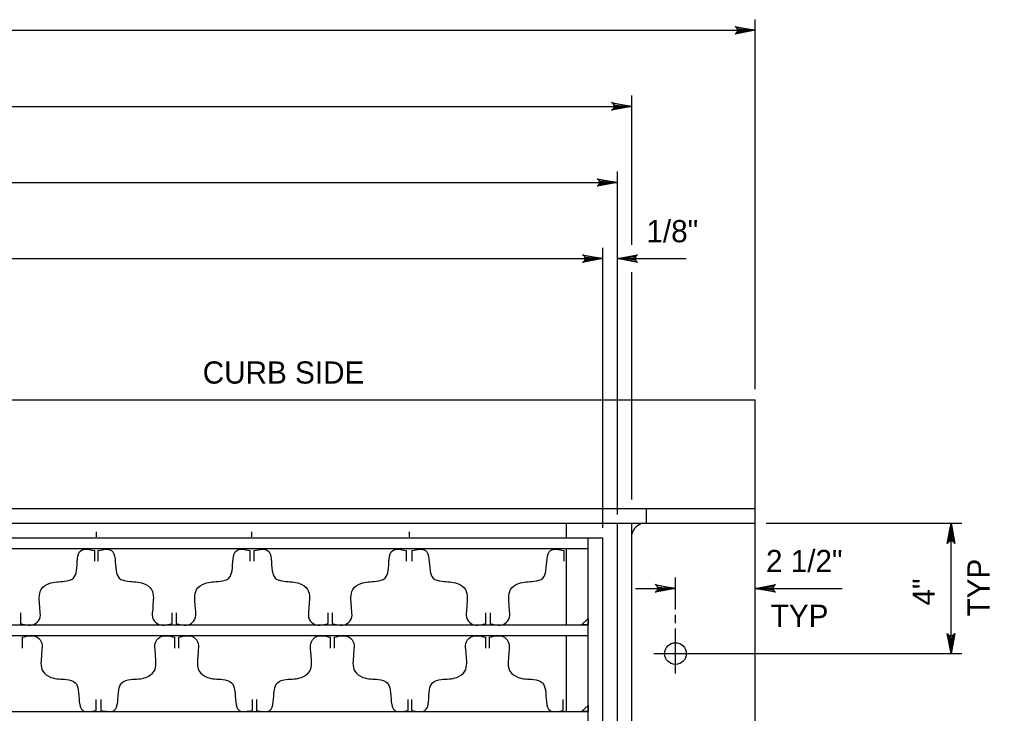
# Model space of a CAD drawing. Extents: x 0.71 to 8.05, y -5.67 to 4.31.
# Drawn here: x 5.033 to 7.656, y 2.355 to 4.233 of the extents above; entities that cross this region are included whole.
import ezdxf

# ---------------------------------------------------------------- set-up
doc = ezdxf.new("R2010")
doc.units = 0
for name, color, linetype in [('DETL-DIMS', 7, 'Continuous'), ('DETL-LINE', 7, 'Continuous'), ('DETL-NOTE', 7, 'Continuous')]:
    doc.layers.add(name, color=color, linetype=linetype)

msp = doc.modelspace()

# ---------------------------------------------------------------- linework, layer by layer
at = {"layer": 'DETL-DIMS'}
for p, q in [((7.0228, 3.233), (7.0228, 4.233)), ((2.1992, 4.2036), (7.0228, 4.2036)), ((6.6892, 3.6228), (6.6892, 4.0271)), ((2.5328, 3.9977), (6.6892, 3.9977)), ((6.6498, 2.8936), (6.6498, 3.8213)), ((2.5722, 3.7918), (6.6498, 3.7918)), ((6.6104, 2.8572), (6.6104, 3.6154)), ((2.6116, 3.586), (6.6104, 3.586)), ((6.6498, 3.586), (6.8363, 3.586)), ((6.6892, 2.934), (6.6892, 3.5492)), ((7.0522, 2.8701), (7.5816, 2.8701)), ((7.5522, 2.5171), (7.5522, 2.8701)), ((6.8069, 2.6365), (6.8069, 2.723)), ((6.6992, 2.6936), (6.8069, 2.6936)), ((7.0228, 2.6936), (7.2581, 2.6936)), ((6.8069, 2.5994), (6.8069, 2.6221)), ((6.8069, 2.4632), (6.8069, 2.5849)), ((6.7481, 2.5171), (7.5816, 2.5171))]:
    msp.add_line(p, q, dxfattribs=at)
for points in [[(7.0228, 4.2036), (6.9679, 4.1933), (6.9722, 4.1963), (6.9743, 4.1999), (6.975, 4.2036), (6.9743, 4.2073), (6.9722, 4.211), (6.9679, 4.2139), (7.0228, 4.2036), (6.9722, 4.211), (6.9743, 4.2073), (7.0228, 4.2036), (6.975, 4.2036), (6.9743, 4.1999), (7.0228, 4.2036), (6.9722, 4.1963)], [(6.6892, 3.9977), (6.6344, 3.9875), (6.6386, 3.9904), (6.6408, 3.9941), (6.6414, 3.9977), (6.6408, 4.0014), (6.6386, 4.0051), (6.6344, 4.008), (6.6892, 3.9977), (6.6386, 4.0051), (6.6408, 4.0014), (6.6892, 3.9977), (6.6414, 3.9977), (6.6408, 3.9941), (6.6892, 3.9977), (6.6386, 3.9904)], [(6.6498, 3.7918), (6.595, 3.7816), (6.5992, 3.7845), (6.6014, 3.7882), (6.602, 3.7918), (6.6014, 3.7955), (6.5992, 3.7992), (6.595, 3.8021), (6.6498, 3.7918), (6.5992, 3.7992), (6.6014, 3.7955), (6.6498, 3.7918), (6.602, 3.7918), (6.6014, 3.7882), (6.6498, 3.7918), (6.5992, 3.7845)], [(6.6104, 3.586), (6.5556, 3.5757), (6.5598, 3.5786), (6.562, 3.5823), (6.5626, 3.586), (6.562, 3.5896), (6.5598, 3.5933), (6.5556, 3.5962), (6.6104, 3.586), (6.5598, 3.5933), (6.562, 3.5896), (6.6104, 3.586), (6.5626, 3.586), (6.562, 3.5823), (6.6104, 3.586), (6.5598, 3.5786)], [(6.6498, 3.586), (6.7046, 3.5962), (6.7004, 3.5933), (6.6982, 3.5896), (6.6976, 3.586), (6.6982, 3.5823), (6.7004, 3.5786), (6.7046, 3.5757), (6.6498, 3.586), (6.7004, 3.5786), (6.6982, 3.5823), (6.6498, 3.586), (6.6976, 3.586), (6.6982, 3.5896), (6.6498, 3.586), (6.7004, 3.5933)], [(7.5522, 2.8701), (7.5625, 2.8153), (7.5595, 2.8195), (7.5558, 2.8217), (7.5522, 2.8223), (7.5485, 2.8217), (7.5448, 2.8195), (7.5419, 2.8153), (7.5522, 2.8701), (7.5448, 2.8195), (7.5485, 2.8217), (7.5522, 2.8701), (7.5522, 2.8223), (7.5558, 2.8217), (7.5522, 2.8701), (7.5595, 2.8195)], [(6.8069, 2.6936), (6.752, 2.6833), (6.7563, 2.6863), (6.7585, 2.6899), (6.7591, 2.6936), (6.7585, 2.6973), (6.7563, 2.701), (6.752, 2.7039), (6.8069, 2.6936), (6.7563, 2.701), (6.7585, 2.6973), (6.8069, 2.6936), (6.7591, 2.6936), (6.7585, 2.6899), (6.8069, 2.6936), (6.7563, 2.6863)], [(7.0228, 2.6936), (7.0776, 2.7039), (7.0734, 2.701), (7.0712, 2.6973), (7.0706, 2.6936), (7.0712, 2.6899), (7.0734, 2.6863), (7.0776, 2.6833), (7.0228, 2.6936), (7.0734, 2.6863), (7.0712, 2.6899), (7.0228, 2.6936), (7.0706, 2.6936), (7.0712, 2.6973), (7.0228, 2.6936), (7.0734, 2.701)], [(7.5522, 2.5171), (7.5419, 2.572), (7.5448, 2.5677), (7.5485, 2.5656), (7.5522, 2.5649), (7.5558, 2.5656), (7.5595, 2.5677), (7.5625, 2.572), (7.5522, 2.5171), (7.5595, 2.5677), (7.5558, 2.5656), (7.5522, 2.5171), (7.5522, 2.5649), (7.5485, 2.5656), (7.5522, 2.5171), (7.5448, 2.5677)]]:
    msp.add_lwpolyline(points, dxfattribs=at)
at = {"layer": 'DETL-LINE'}
for p, q in [((2.1992, 3.2036), (7.0228, 3.2036)), ((7.0228, 0.546), (7.0228, 3.2036)), ((2.1992, 2.9095), (7.0228, 2.9095)), ((6.7286, 2.8701), (6.7286, 2.9095)), ((2.1992, 2.8701), (7.0228, 2.8701)), ((6.5122, 2.8307), (6.5122, 2.8701)), ((6.6498, 0.8795), (6.6498, 2.8701)), ((6.6892, 0.8795), (6.6892, 2.8701)), ((5.2412, 2.8331), (5.2412, 2.8468)), ((5.6618, 2.8331), (5.6618, 2.8468)), ((6.0874, 2.8331), (6.0874, 2.8468)), ((2.6116, 2.8307), (6.6104, 2.8307)), ((6.571, 0.9189), (6.571, 2.8307)), ((6.571, 0.9189), (6.571, 2.8307)), ((6.6104, 0.9189), (6.6104, 2.8307)), ((2.651, 2.8013), (6.571, 2.8013)), ((5.2358, 2.7965), (5.2358, 2.7671)), ((5.2461, 2.7671), (5.2461, 2.7965)), ((5.6565, 2.7965), (5.6565, 2.7671)), ((5.6682, 2.7671), (5.6682, 2.7965)), ((6.0785, 2.7965), (6.0785, 2.7671)), ((6.0949, 2.7671), (6.0949, 2.7965)), ((6.5052, 2.7965), (6.5052, 2.7671)), ((6.5122, 2.5954), (6.5122, 2.8013)), ((5.0363, 2.6279), (5.0363, 2.5984)), ((5.4457, 2.5984), (5.4457, 2.6279)), ((5.4569, 2.6279), (5.4569, 2.5984)), ((5.8677, 2.5984), (5.8677, 2.6279)), ((5.879, 2.6279), (5.879, 2.5984)), ((6.2944, 2.5984), (6.2944, 2.6279)), ((6.3057, 2.6279), (6.3057, 2.5984)), ((2.651, 2.5954), (6.571, 2.5954)), ((2.651, 2.566), (6.571, 2.566)), ((5.041, 2.5321), (5.041, 2.5615)), ((5.4527, 2.5615), (5.4527, 2.5321)), ((5.464, 2.5321), (5.464, 2.5615)), ((5.8734, 2.5615), (5.8734, 2.5321)), ((5.8846, 2.5321), (5.8846, 2.5615)), ((6.2929, 2.5615), (6.2929, 2.5321)), ((6.3041, 2.5321), (6.3041, 2.5615)), ((6.5122, 2.3601), (6.5122, 2.566)), ((5.2406, 2.3634), (5.2406, 2.3929)), ((5.2532, 2.3929), (5.2532, 2.3634)), ((5.6635, 2.3634), (5.6635, 2.3929)), ((5.6738, 2.3929), (5.6738, 2.3634)), ((6.0842, 2.3634), (6.0842, 2.3929)), ((6.0933, 2.3929), (6.0933, 2.3634)), ((6.5037, 2.3634), (6.5037, 2.3929)), ((2.651, 2.3601), (6.571, 2.3601))]:
    msp.add_line(p, q, dxfattribs=at)
for points in [[(6.5525, 2.5954), (6.571, 2.6118), (6.571, 2.5954)], [(6.5525, 2.3601), (6.571, 2.3765), (6.571, 2.3601)]]:
    msp.add_lwpolyline(points, close=True, dxfattribs=at)
msp.add_circle((6.8069, 2.5171), 0.0294, dxfattribs=at)
msp.add_arc((6.7287, 2.8306), 0.0407, 104.2782, 165.7218, dxfattribs=at)
for points in [[(5.0363, 2.5984), (5.0766, 2.5985), (5.089, 2.6158), (5.0885, 2.6372), (5.0881, 2.6449), (5.0917, 2.6903), (5.1135, 2.707), (5.1553, 2.7129), (5.1791, 2.7216), (5.1873, 2.7409), (5.1999, 2.7965), (5.2358, 2.7965)], [(5.0363, 2.5984), (5.0766, 2.5985), (5.089, 2.6158), (5.0885, 2.6372), (5.0881, 2.6449), (5.0917, 2.6903), (5.1135, 2.707), (5.1553, 2.7129), (5.1791, 2.7216), (5.1873, 2.7409), (5.1999, 2.7965), (5.2358, 2.7965)], [(5.2461, 2.7965), (5.282, 2.7965), (5.2946, 2.7409), (5.3028, 2.7216), (5.3266, 2.7129), (5.3684, 2.707), (5.3902, 2.6903), (5.3938, 2.6449), (5.3934, 2.6372), (5.3929, 2.6158), (5.4053, 2.5985), (5.4457, 2.5984)], [(5.2461, 2.7965), (5.282, 2.7965), (5.2946, 2.7409), (5.3028, 2.7216), (5.3266, 2.7129), (5.3684, 2.707), (5.3902, 2.6903), (5.3938, 2.6449), (5.3934, 2.6372), (5.3929, 2.6158), (5.4053, 2.5985), (5.4457, 2.5984)], [(5.4569, 2.5984), (5.4973, 2.5985), (5.5096, 2.6158), (5.5092, 2.6372), (5.5087, 2.6449), (5.5123, 2.6903), (5.5342, 2.707), (5.5759, 2.7129), (5.5997, 2.7216), (5.6079, 2.7409), (5.6205, 2.7965), (5.6565, 2.7965)], [(5.4569, 2.5984), (5.4973, 2.5985), (5.5096, 2.6158), (5.5092, 2.6372), (5.5087, 2.6449), (5.5123, 2.6903), (5.5342, 2.707), (5.5759, 2.7129), (5.5997, 2.7216), (5.6079, 2.7409), (5.6205, 2.7965), (5.6565, 2.7965)], [(5.6682, 2.7965), (5.7041, 2.7965), (5.7167, 2.7409), (5.7249, 2.7216), (5.7487, 2.7129), (5.7905, 2.707), (5.8123, 2.6903), (5.8159, 2.6449), (5.8154, 2.6372), (5.815, 2.6158), (5.8274, 2.5985), (5.8677, 2.5984)], [(5.6682, 2.7965), (5.7041, 2.7965), (5.7167, 2.7409), (5.7249, 2.7216), (5.7487, 2.7129), (5.7905, 2.707), (5.8123, 2.6903), (5.8159, 2.6449), (5.8154, 2.6372), (5.815, 2.6158), (5.8274, 2.5985), (5.8677, 2.5984)], [(5.879, 2.5984), (5.9193, 2.5985), (5.9317, 2.6158), (5.9312, 2.6372), (5.9308, 2.6449), (5.9344, 2.6903), (5.9562, 2.707), (5.998, 2.7129), (6.0218, 2.7216), (6.03, 2.7409), (6.0426, 2.7965), (6.0785, 2.7965)], [(5.879, 2.5984), (5.9193, 2.5985), (5.9317, 2.6158), (5.9312, 2.6372), (5.9308, 2.6449), (5.9344, 2.6903), (5.9562, 2.707), (5.998, 2.7129), (6.0218, 2.7216), (6.03, 2.7409), (6.0426, 2.7965), (6.0785, 2.7965)], [(6.0949, 2.7965), (6.1308, 2.7965), (6.1434, 2.7409), (6.1516, 2.7216), (6.1754, 2.7129), (6.2172, 2.707), (6.239, 2.6903), (6.2426, 2.6449), (6.2421, 2.6372), (6.2417, 2.6158), (6.2541, 2.5985), (6.2944, 2.5984)], [(6.0949, 2.7965), (6.1308, 2.7965), (6.1434, 2.7409), (6.1516, 2.7216), (6.1754, 2.7129), (6.2172, 2.707), (6.239, 2.6903), (6.2426, 2.6449), (6.2421, 2.6372), (6.2417, 2.6158), (6.2541, 2.5985), (6.2944, 2.5984)], [(6.3057, 2.5984), (6.346, 2.5985), (6.3584, 2.6158), (6.3579, 2.6372), (6.3575, 2.6449), (6.3611, 2.6903), (6.3829, 2.707), (6.4247, 2.7129), (6.4485, 2.7216), (6.4567, 2.7409), (6.4693, 2.7965), (6.5052, 2.7965)], [(6.3057, 2.5984), (6.346, 2.5985), (6.3584, 2.6158), (6.3579, 2.6372), (6.3575, 2.6449), (6.3611, 2.6903), (6.3829, 2.707), (6.4247, 2.7129), (6.4485, 2.7216), (6.4567, 2.7409), (6.4693, 2.7965), (6.5052, 2.7965)], [(5.041, 2.5615), (5.0814, 2.5615), (5.0937, 2.5442), (5.0933, 2.5227), (5.0928, 2.515), (5.0964, 2.4696), (5.1183, 2.4529), (5.1601, 2.4471), (5.1839, 2.4384), (5.192, 2.4191), (5.2046, 2.3634), (5.2406, 2.3634)], [(5.2532, 2.3634), (5.2891, 2.3634), (5.3017, 2.4191), (5.3099, 2.4384), (5.3337, 2.4471), (5.3755, 2.4529), (5.3973, 2.4696), (5.4009, 2.515), (5.4005, 2.5227), (5.4, 2.5442), (5.4124, 2.5615), (5.4527, 2.5615)], [(5.464, 2.5615), (5.5043, 2.5615), (5.5167, 2.5442), (5.5162, 2.5227), (5.5158, 2.515), (5.5194, 2.4696), (5.5412, 2.4529), (5.583, 2.4471), (5.6068, 2.4384), (5.615, 2.4191), (5.6276, 2.3634), (5.6635, 2.3634)], [(5.6738, 2.3634), (5.7098, 2.3634), (5.7224, 2.4191), (5.7305, 2.4384), (5.7543, 2.4471), (5.7961, 2.4529), (5.818, 2.4696), (5.8216, 2.515), (5.8211, 2.5227), (5.8207, 2.5442), (5.833, 2.5615), (5.8734, 2.5615)], [(5.8846, 2.5615), (5.925, 2.5615), (5.9373, 2.5442), (5.9369, 2.5227), (5.9364, 2.515), (5.94, 2.4696), (5.9619, 2.4529), (6.0037, 2.4471), (6.0275, 2.4384), (6.0356, 2.4191), (6.0482, 2.3634), (6.0842, 2.3634)], [(6.0933, 2.3634), (6.1293, 2.3634), (6.1419, 2.4191), (6.15, 2.4384), (6.1738, 2.4471), (6.2156, 2.4529), (6.2375, 2.4696), (6.2411, 2.515), (6.2406, 2.5227), (6.2402, 2.5442), (6.2525, 2.5615), (6.2929, 2.5615)], [(6.3041, 2.5615), (6.3445, 2.5615), (6.3568, 2.5442), (6.3564, 2.5227), (6.356, 2.515), (6.3595, 2.4696), (6.3814, 2.4529), (6.4232, 2.4471), (6.447, 2.4384), (6.4551, 2.4191), (6.4677, 2.3634), (6.5037, 2.3634)]]:
    msp.add_spline(points, degree=3, dxfattribs=at)

# ---------------------------------------------------------------- texts
at = {"layer": 'DETL-NOTE'}
for s, p in [('1/8"', (6.7284, 3.6301)), ('CURB SIDE', (5.5287, 3.2477)), ('2 1/2"', (7.0517, 2.7377)), ('TYP', (7.0645, 2.5895))]:
    msp.add_text(s, height=0.06, dxfattribs=at).set_placement(p)
for s, p in [('TYP', (7.6563, 2.6177)), ('4"', (7.5081, 2.6473))]:
    msp.add_text(s, height=0.06, rotation=90, dxfattribs=at).set_placement(p)

doc.saveas('drawing.dxf')
